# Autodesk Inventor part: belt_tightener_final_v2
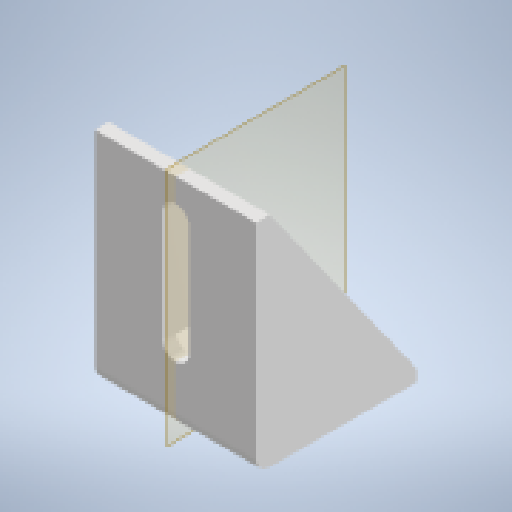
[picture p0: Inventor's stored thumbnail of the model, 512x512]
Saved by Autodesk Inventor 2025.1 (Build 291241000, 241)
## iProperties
Created: 2024-11
Part Number: belt_tightener_final_v2
Material: Generic
Document SubType Name: Modeling
Designer: mansa
Density: 1 g/cm^3
Appearance: Default
Author: mansa
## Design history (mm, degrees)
sketch "Sketch1"
  geometry: L1 (0, 0)-(35, 0); L2 (35, 0)-(35, 35); L3 (35, 35)-(0, 35); L4 (0, 35)-(0, 0)
  constraints: 8 end point, 2 parallel, 1 horizontal, 1 perpendicular
  dimensions: "d0" = 35 distance of L1.end L2.end; "d1" = 35 distance of L2.end L3.end (= d0)
extrude "Extrusion1" new body sketch "Sketch1" distance "d2" = 2.5; taper "d3" = 0 deg
sketch "Sketch2"
  geometry: L1 (-35, -35)-(0, -35) reference; L2 (-17.5, -35)-(-17.5, 0); L3 (0, 0)-(-35, 0) reference; L4 (-35, 0)-(-35, -35) reference; L5 (-35, -17.5)-(0, -17.5); L6 (0, -35)-(0, 0) reference; L7 (-17.5, -5)-(-17.5, -25); L8 (-14.6, -5)-(-14.6, -25); L9 (-20.4, -25)-(-20.4, -5); A1 r 2.9 centre (-17.5, -5) between (-14.6, -5) and (-20.4, -5); A2 r 2.9 centre (-17.5, -25) between (-20.4, -25) and (-14.6, -25); 1 further point
  constraints: 12 end point, 5 midpoint, 4 point on circle, 4 tangent, 2 centre point, 2 point on line, 1 parallel
  dimensions: "d33" = 2.9 radius of A2; "d34" = 20 distance of L7.start L7.end; "d35" = 2.5 distance from line of point (-17.5, -15) L5
sketch "Sketch3"
  geometry: L1 (-35, -35)-(0, -35) reference; L2 (0, -35)-(0, 0) reference; L3 (-35, -35)-(0, -35); L4 (0, -35)-(0, -32); L5 (0, -32)-(-35, -32); L6 (-35, -32)-(-35, -35)
  constraints: 8 end point, 2 parallel, 1 horizontal, 1 perpendicular, 1 point on line
  dimensions: "d7" = 3 distance between parallel lines of L1 L5
extrude "Extrusion3" join sketch "Sketch3" distance "d8" = 45; taper "d9" = 0 deg
fillet "Fillet3" dims "d21" = 3
sketch "Sketch7"
  geometry: L1 (0, 42)-(35, 42) reference; L2 (17.5, 42)-(17.5, 0); L3 (35, 0)-(0, 0) reference; L4 (17.5, 10)-(17.5, 34); L5 (20.4, 10)-(20.4, 34); L6 (14.6, 34)-(14.6, 10); A1 r 2.9 centre (17.5, 10) between (14.6, 10) and (20.4, 10); A2 r 2.9 centre (17.5, 34) between (20.4, 34) and (14.6, 34); 2 further points
  constraints: 10 end point, 4 point on circle, 4 tangent, 3 midpoint, 2 centre point, 2 point on line, 1 parallel
  dimensions: "d38" = 2.9 radius of A1; "d39" = 24 distance of L4.end L4.start; "d40" = 20 distance from line of L1 point (17.5, 22)
extrude "Extrusion8" cut sketch "Sketch2" distance "d36" = 2.5; taper "d37" = 0 deg
extrude "Extrusion9" cut sketch "Sketch7" distance "d41" = 10.5; taper "d42" = 0 deg
sketch "Sketch8"
  geometry: L1 (29, 2.5)-(0, 2.5) reference; L2 (32, 5.5)-(32, 47.5) reference; L3 (0, 2.5)-(32, 47.5); L4 (32, 47.5)-(32, 5.5); A1 r 3 centre (29, 5.5) between (29, 2.5) and (32, 5.5) reference; 1 further point
  constraints: 4 end point, 1 collinear
extrude "Extrusion10" join sketch "Sketch8" distance "d43" = 2.25; taper "d44" = 0 deg
workplane "Work Plane1"
mirror "Mirror1"
workplane "Work Plane2"
body "Solid1"
